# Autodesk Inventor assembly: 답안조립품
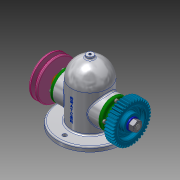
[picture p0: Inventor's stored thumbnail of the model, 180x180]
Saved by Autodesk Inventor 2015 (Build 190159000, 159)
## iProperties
Created: 2019-11
Part Number: 답안조립품
Document SubType Name: Assembly
Designer: Administrator
Author: Administrator
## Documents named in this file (14)
- C:\Users\Administrator\Desktop\491104V1018\답안조립품.iam
- C:\Users\Administrator\Desktop\491104V1018\본체.ipt
- C:\Users\Administrator\Desktop\491104V1018\커버.ipt
- C:\Users\Administrator\Desktop\491104V1018\오일 실 26 38 8.ipt
- C:\Users\Administrator\Desktop\491104V1018\베어링 6203.ipt
- C:\Users\Administrator\Desktop\491104V1018\부시.ipt
- C:\Users\Administrator\Desktop\491104V1018\볼트 M4.ipt
- C:\Users\Administrator\Desktop\491104V1018\축.ipt
- C:\Users\Administrator\Desktop\491104V1018\키 5x5x12.ipt
- C:\Users\Administrator\Desktop\491104V1018\V-벨트풀리.ipt
- V-벨트풀리.ipt
- C:\Users\Administrator\Desktop\491104V1018\스퍼기어.ipt
- C:\Users\Administrator\Desktop\491104V1018\너트 M12x1.25.ipt
- C:\Users\Administrator\Desktop\491104V1018\와셔 12x24.ipt
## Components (1 placed, 1 different names)
1. V-벨트풀리:1
